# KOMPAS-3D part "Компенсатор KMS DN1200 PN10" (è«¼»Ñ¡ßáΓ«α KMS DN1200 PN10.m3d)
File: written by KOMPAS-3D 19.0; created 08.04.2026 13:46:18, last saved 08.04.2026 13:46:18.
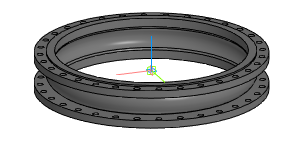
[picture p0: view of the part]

Document properties: Автор: Энергия; Полное имя файла: Z:\3.Личные\kachalov\3d для проектировщиков\7.1 Компенсатор\stp_Компенсатор KSM\Компенсатор KMS DN1200 PN10.m3d

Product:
- Part/product: Компенсатор KMS DN1200 PN10

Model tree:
1. Операция без истории:1  (labels: Компенсатор KMS DN1200 PN10)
